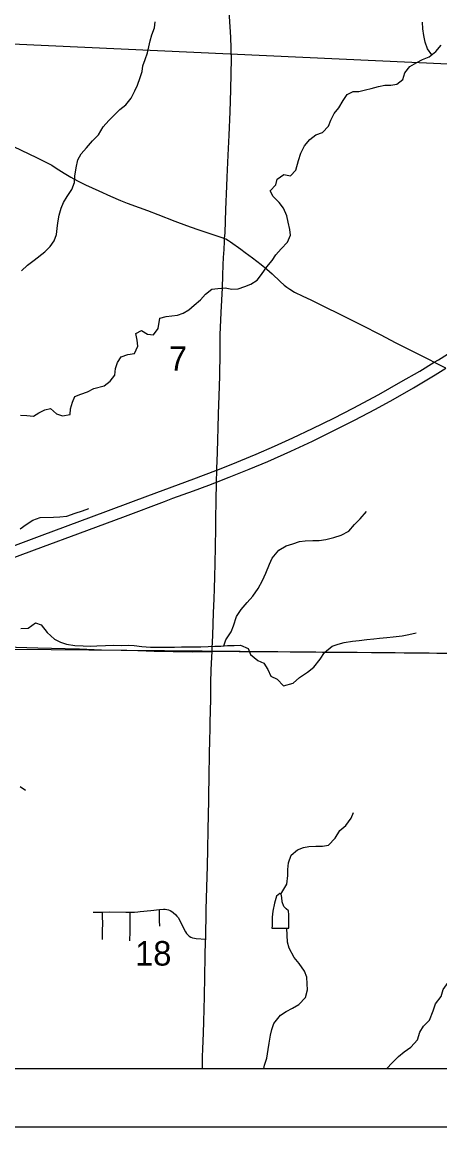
# Model space of a CAD drawing. Extents: x 0 to 34, y 0 to 22.
# Drawn here: x 3.412 to 4.127, y 14 to 15.888 of the extents above; entities that cross this region are included whole.
import ezdxf

# ---------------------------------------------------------------- set-up
doc = ezdxf.new("R2010")
doc.units = 0
for name, color, linetype in [('Default', 7, 'Continuous'), ('GM_X_County_Road', 7, 'Continuous'), ('GM_X_Interstate_Route', 7, 'Continuous'), ('GM_X_Minor_Lake', 7, 'Continuous'), ('GM_X_Minor_River', 7, 'Continuous'), ('GM_X_Section', 7, 'Continuous'), ('GM_X_Section_Text', 7, 'Continuous'), ('GM_X_State_Route', 7, 'Continuous'), ('GM_X_Township_Road', 7, 'Continuous'), ('SH_Cut_Line', 7, 'Continuous'), ('SH_Data', 7, 'Continuous')]:
    doc.layers.add(name, color=color, linetype=linetype)

msp = doc.modelspace()

# ---------------------------------------------------------------- linework, layer by layer
at = {"layer": 'Default'}
msp.add_lwpolyline([(3.1977, 14.1), (4.2188, 14.1), (4.2381, 14.8083), (3.2026, 14.8175)], close=True, dxfattribs=at)
at = {"layer": 'GM_X_County_Road'}
for points in [[(3.3832, 14.8203), (3.4391, 14.8187), (3.4857, 14.8175), (3.5105, 14.8167), (3.5478, 14.8153), (3.5819, 14.8144), (3.6099, 14.8139), (3.6382, 14.8131), (3.6542, 14.8128), (3.6706, 14.8125), (3.6856, 14.8121), (3.7033, 14.8116), (3.7278, 14.8121), (3.7371, 14.8123)], [(3.7371, 14.8123), (3.7464, 14.8126), (3.7587, 14.8126), (3.7836, 14.8124), (3.8053, 14.8122), (3.8344, 14.812), (3.8706, 14.8118), (3.8962, 14.8116), (3.9262, 14.8114), (3.9511, 14.8109), (3.9666, 14.8109), (3.9852, 14.811), (4.01, 14.8107), (4.0504, 14.8104), (4.0659, 14.8101), (4.0876, 14.8099), (4.1031, 14.8098), (4.1217, 14.8097), (4.1652, 14.8095)]]:
    msp.add_lwpolyline(points, dxfattribs=at)
at = {"layer": 'GM_X_Interstate_Route'}
for points in [[(4.6269, 16.8701), (3.6554, 16.8713), (3.6203, 16.8714), (3.2115, 16.8719), (3.2111, 16.7578), (3.2098, 15.7617), (3.2042, 14.9221), (3.2041, 14.9016), (3.2037, 14.7782), (3.2011, 14.1), (8.2568, 14.1)], [(3.3853, 14.9885), (3.4144, 14.9993), (3.4465, 15.0112), (3.531, 15.0424), (3.627, 15.0785), (3.7057, 15.1075), (3.7436, 15.1216), (3.7455, 15.1223), (3.7697, 15.1318), (3.8128, 15.1496), (3.8442, 15.163), (3.8754, 15.1771), (3.9091, 15.1931), (3.9453, 15.211), (3.9785, 15.2281), (4.0223, 15.2516), (4.0603, 15.2729), (4.0926, 15.2915), (4.1173, 15.3065), (4.1245, 15.3109), (4.1614, 15.334)], [(3.742, 15.1007), (3.7449, 15.1018), (3.7663, 15.11), (3.8009, 15.1238), (3.8324, 15.1371), (3.8721, 15.1547), (3.9087, 15.1717), (3.9478, 15.1908), (3.981, 15.2076), (4.0168, 15.2263), (4.0467, 15.2427), (4.0817, 15.2628), (4.1191, 15.2849), (4.1373, 15.2963)], [(3.3237, 14.9455), (3.449, 14.9917), (3.5073, 15.0132), (3.5889, 15.0436), (3.6559, 15.0684), (3.6703, 15.0741), (3.6878, 15.0806), (3.7054, 15.0868), (3.7316, 15.0966), (3.742, 15.1007)]]:
    msp.add_lwpolyline(points, dxfattribs=at)
at = {"layer": 'GM_X_Minor_Lake'}
for points in [[(3.8687, 14.3394), (3.8683, 14.353), (3.8686, 14.3621), (3.8678, 14.3693), (3.864, 14.3727), (3.8598, 14.3765), (3.8572, 14.3845), (3.8568, 14.392), (3.8556, 14.3974), (3.853, 14.3985), (3.8473, 14.3943), (3.8439, 14.3821), (3.8413, 14.3685), (3.8398, 14.3582), (3.8398, 14.3438)], [(3.8687, 14.3393), (3.8683, 14.353), (3.8686, 14.3621), (3.8678, 14.3693), (3.864, 14.3727), (3.8598, 14.3765), (3.8572, 14.3845), (3.8568, 14.392), (3.8556, 14.3974), (3.853, 14.3985), (3.8473, 14.3943), (3.8439, 14.3821), (3.8413, 14.3685), (3.8398, 14.3582), (3.8398, 14.3438)], [(3.8398, 14.3438), (3.8396, 14.3396), (3.8687, 14.3394)]]:
    msp.add_lwpolyline(points, dxfattribs=at)
at = {"layer": 'GM_X_Minor_River'}
for points in [[(3.6175, 15.8032), (3.619, 15.8131), (3.6225, 15.8237), (3.6268, 15.835), (3.6292, 15.8456), (3.6311, 15.8555), (3.6339, 15.8657), (3.6385, 15.8782), (3.6398, 15.888)], [(4.1131, 15.832), (4.1059, 15.8421), (4.1018, 15.8532), (4.0992, 15.8646), (4.0975, 15.8764), (4.0972, 15.8877)], [(3.8649, 15.5565), (3.8593, 15.5698), (3.8518, 15.5794), (3.8417, 15.5897), (3.8365, 15.5996), (3.846, 15.6094), (3.8484, 15.6196), (3.8598, 15.6271), (3.8712, 15.6251), (3.8803, 15.6349), (3.885, 15.6511), (3.8889, 15.6636), (3.8954, 15.6765), (3.9046, 15.687), (3.9149, 15.6952), (3.9259, 15.6993), (3.9362, 15.7098), (3.9405, 15.72), (3.9463, 15.7314), (3.9539, 15.7412), (3.9616, 15.754), (3.9685, 15.7642), (3.9784, 15.769), (3.9882, 15.7693), (3.9996, 15.7718), (4.0095, 15.774), (4.0216, 15.7777), (4.0326, 15.7802), (4.0432, 15.7801), (4.0535, 15.7819), (4.0634, 15.7898), (4.0669, 15.8008), (4.0753, 15.8117), (4.0875, 15.8184), (4.0974, 15.824), (4.1088, 15.8284), (4.1198, 15.8374), (4.129, 15.8483)], [(3.4112, 15.4626), (3.4215, 15.4724), (3.433, 15.481), (3.4509, 15.4949), (3.4604, 15.5042), (3.4669, 15.514), (3.4708, 15.5246), (3.4724, 15.5349), (3.4733, 15.5447), (3.4756, 15.558), (3.4788, 15.5697), (3.483, 15.5795), (3.4892, 15.5897), (3.4972, 15.6018), (3.5019, 15.6135), (3.5023, 15.6245), (3.5044, 15.6389), (3.5075, 15.6525), (3.5133, 15.6627), (3.5221, 15.6729), (3.5328, 15.6849), (3.5431, 15.6951), (3.5511, 15.7086), (3.5603, 15.7196), (3.5699, 15.7286), (3.5794, 15.7383), (3.5897, 15.7462), (3.5989, 15.7579), (3.6051, 15.77), (3.6097, 15.7802), (3.614, 15.793), (3.6175, 15.8032)], [(3.4095, 15.216), (3.4205, 15.2155), (3.4315, 15.2146), (3.441, 15.2198), (3.4509, 15.2254), (3.4607, 15.2272), (3.4713, 15.2184), (3.4811, 15.2149), (3.4943, 15.217), (3.4952, 15.2269), (3.4983, 15.2383), (3.5022, 15.2481), (3.5128, 15.2522), (3.5238, 15.2562), (3.5349, 15.2614), (3.5527, 15.2662), (3.5626, 15.2744), (3.5706, 15.2846), (3.5719, 15.2956), (3.5754, 15.3058), (3.5819, 15.316), (3.5929, 15.3197), (3.6043, 15.3215), (3.6104, 15.3339), (3.609, 15.3442), (3.6065, 15.3556), (3.6164, 15.3608), (3.6269, 15.3543), (3.6371, 15.3534), (3.6448, 15.3643), (3.648, 15.3818), (3.6586, 15.3847), (3.6681, 15.3857), (3.6783, 15.3868), (3.6878, 15.3905), (3.6973, 15.3961), (3.7068, 15.4043), (3.7175, 15.4133), (3.7259, 15.4231), (3.7366, 15.4314), (3.7468, 15.4324), (3.7593, 15.4334), (3.7711, 15.4314), (3.782, 15.4321), (3.7931, 15.4357), (3.8037, 15.4398), (3.8144, 15.4469), (3.822, 15.4567), (3.8308, 15.4695), (3.84, 15.4804), (3.8462, 15.4902), (3.8553, 15.5004), (3.8664, 15.5117), (3.8714, 15.5234), (3.87, 15.5336), (3.8675, 15.5458), (3.8649, 15.5565)], [(3.4088, 15.0221), (3.419, 15.0293), (3.4308, 15.0369), (3.4429, 15.0415), (3.4657, 15.0416), (3.4767, 15.0424), (3.4888, 15.0435), (3.5032, 15.0485), (3.5157, 15.0527), (3.5263, 15.0566)], [(3.7571, 14.8218), (3.7606, 14.8323), (3.7701, 14.846), (3.7738, 14.8562), (3.7787, 14.8722), (3.787, 14.8843), (3.7973, 14.8958), (3.8067, 14.9068), (3.8158, 14.9197), (3.8233, 14.9334), (3.829, 14.9459), (3.8354, 14.9615), (3.8399, 14.9718), (3.8516, 14.9855), (3.8641, 14.9927), (3.8755, 14.9965), (3.8868, 15), (3.8963, 15.0015), (3.9096, 15.002), (3.9202, 15.002), (3.932, 15.0039), (3.9452, 15.007), (3.9578, 15.0108), (3.971, 15.0181), (3.9808, 15.0295), (3.9903, 15.039), (4.0013, 15.0512)], [(3.4101, 14.8517), (3.4226, 14.8521), (3.4351, 14.8613), (3.4446, 14.8579), (3.4552, 14.845), (3.4678, 14.8333), (3.4777, 14.828), (3.4883, 14.825), (3.5023, 14.8228), (3.5168, 14.8217), (3.5289, 14.8213), (3.5399, 14.8217), (3.5547, 14.8225), (3.5687, 14.823), (3.5824, 14.8226), (3.5934, 14.823), (3.604, 14.8223), (3.6173, 14.8208), (3.6321, 14.8197), (3.6484, 14.8194), (3.6579, 14.8194), (3.6727, 14.8199), (3.6848, 14.8203), (3.7182, 14.8204), (3.7307, 14.8208), (3.7421, 14.8212), (3.752, 14.8212), (3.7637, 14.8224), (3.7751, 14.8228), (3.7857, 14.8232), (3.799, 14.8176), (3.8032, 14.807), (3.8154, 14.7968), (3.8256, 14.7926), (3.8325, 14.7817), (3.8378, 14.7699), (3.8488, 14.765), (3.8595, 14.7537), (3.8758, 14.7579), (3.8868, 14.7678), (3.9004, 14.7769), (3.9114, 14.7853), (3.9223, 14.7994), (3.9295, 14.8104), (3.9428, 14.8211), (3.953, 14.8249), (3.9632, 14.8276), (3.9773, 14.8299), (3.989, 14.8311), (4.0019, 14.8326), (4.0137, 14.8338), (4.0235, 14.835), (4.036, 14.8362), (4.047, 14.8373), (4.0626, 14.8393), (4.0736, 14.8412)], [(4.0736, 14.8412), (4.0865, 14.8443)], [(3.4086, 14.5815), (3.4181, 14.5755)], [(3.8548, 14.3977), (3.865, 14.4148), (3.8669, 14.4293), (3.8669, 14.4395), (3.868, 14.4513), (3.8725, 14.4642), (3.8831, 14.4733), (3.8933, 14.4771), (3.9028, 14.4791), (3.9146, 14.4799), (3.9259, 14.4799), (3.9362, 14.4811), (3.9479, 14.4936), (3.9558, 14.5066), (3.966, 14.5149), (3.9751, 14.5275), (3.9789, 14.537)], [(3.8255, 14.1), (3.8269, 14.1055), (3.8306, 14.1176), (3.8333, 14.1321), (3.8351, 14.1431), (3.8374, 14.1567), (3.8392, 14.1662), (3.843, 14.1769), (3.8543, 14.1909), (3.8642, 14.1974), (3.8748, 14.2031), (3.8854, 14.2092), (3.8971, 14.221), (3.9005, 14.2343), (3.9001, 14.2446), (3.8993, 14.256), (3.8951, 14.2658), (3.8863, 14.2791), (3.8779, 14.2893), (3.8692, 14.3052), (3.8661, 14.3154), (3.8649, 14.3394)], [(4.0362, 14.1), (4.0363, 14.1), (4.045, 14.1096), (4.056, 14.1202), (4.0658, 14.1282), (4.0772, 14.1362), (4.0885, 14.1488), (4.0926, 14.1621), (4.0987, 14.172), (4.1089, 14.1826), (4.1153, 14.1982), (4.1194, 14.21), (4.1289, 14.2225), (4.1323, 14.2347), (4.1413, 14.2468), (4.1553, 14.2571)]]:
    msp.add_lwpolyline(points, dxfattribs=at)
at = {"layer": 'GM_X_Section'}
for points in [[(4.2148, 16.747), (4.2083, 16.8683), (4.1045, 16.8706), (3.2153, 16.8759), (3.2082, 15.8593), (4.2651, 15.8107), (4.2549, 16), (4.1282, 16), (4.1282, 16.747)], [(3.2082, 15.8593), (4.2651, 15.8107), (4.2381, 14.8083), (3.2026, 14.8175), (3.2029, 14.8323), (3.2075, 15.8525)]]:
    msp.add_lwpolyline(points, close=True, dxfattribs=at)
at = {"layer": 'GM_X_State_Route'}
msp.add_lwpolyline([(3.7206, 14.1), (3.721, 14.1203), (3.7214, 14.1327), (3.7223, 14.1607), (3.7228, 14.1794), (3.7241, 14.2229), (3.7256, 14.2913), (3.7262, 14.3192), (3.7263, 14.321), (3.7273, 14.3715), (3.7282, 14.4088), (3.7291, 14.446), (3.7297, 14.474), (3.7304, 14.5082), (3.7314, 14.5578), (3.7323, 14.6075), (3.7327, 14.6291), (3.733, 14.6383), (3.7333, 14.6598), (3.7337, 14.6815), (3.734, 14.6907), (3.7348, 14.7311), (3.7353, 14.759), (3.7358, 14.7808), (3.7366, 14.8025), (3.7371, 14.8123), (3.7374, 14.818), (3.7383, 14.8397), (3.7389, 14.8597), (3.7398, 14.8783), (3.7408, 14.9024), (3.7413, 14.9193), (3.742, 14.9404), (3.7426, 14.9622), (3.7433, 14.9914), (3.7437, 15.0225), (3.7436, 15.0437), (3.744, 15.0654), (3.7442, 15.0778), (3.7446, 15.0933), (3.7449, 15.1018), (3.7455, 15.1223), (3.7456, 15.1244), (3.7464, 15.1523), (3.7471, 15.1746), (3.7476, 15.194), (3.7483, 15.2183), (3.7492, 15.2493), (3.7502, 15.283), (3.7513, 15.3229), (3.7511, 15.3536), (3.7528, 15.3914), (3.7537, 15.4125), (3.7548, 15.4336), (3.7557, 15.455), (3.7564, 15.4728), (3.757, 15.4853), (3.7576, 15.4993), (3.7583, 15.5127), (3.7587, 15.5179), (3.7593, 15.5277), (3.7609, 15.5673), (3.7625, 15.6075), (3.7632, 15.623), (3.7649, 15.6602), (3.7664, 15.6943), (3.7679, 15.7346), (3.769, 15.7719), (3.77, 15.7998), (3.7704, 15.8246), (3.7701, 15.8432), (3.7693, 15.8618), (3.7655, 15.9238)], dxfattribs=at)
at = {"layer": 'GM_X_Township_Road'}
for points in [[(3.3975, 15.6751), (3.4369, 15.6564), (3.4483, 15.6509), (3.4562, 15.6469), (3.4632, 15.643), (3.4705, 15.6384), (3.4843, 15.6297), (3.4957, 15.6228), (3.5068, 15.6163), (3.5208, 15.6095), (3.5434, 15.5992), (3.5632, 15.5902), (3.5803, 15.583), (3.5919, 15.5786), (3.6123, 15.5711), (3.6269, 15.5656), (3.6442, 15.5588), (3.6733, 15.5477), (3.6936, 15.5399), (3.7111, 15.5337), (3.7539, 15.5199), (3.7587, 15.5179)], [(3.7587, 15.5179), (3.7608, 15.5171), (3.7651, 15.5145), (3.7689, 15.5121), (3.7864, 15.4995), (3.7939, 15.494), (3.8064, 15.4849), (3.8212, 15.4736), (3.8307, 15.4656), (3.84, 15.4573), (3.8535, 15.4446), (3.8604, 15.4384), (3.8653, 15.4346), (3.8704, 15.4311), (3.8784, 15.4264), (3.8923, 15.4196), (3.9063, 15.413), (3.9314, 15.4008), (3.9536, 15.3897), (3.9925, 15.3702), (4.0256, 15.3532), (4.0504, 15.3403), (4.1087, 15.311), (4.1173, 15.3065), (4.1363, 15.2968)], [(3.534, 14.3667), (3.5413, 14.3669), (3.5479, 14.367), (3.5499, 14.367)], [(3.5497, 14.3202), (3.55, 14.3354), (3.5501, 14.3476), (3.55, 14.3597), (3.5499, 14.367)], [(3.5499, 14.367), (3.5616, 14.3672), (3.5894, 14.3669), (3.5971, 14.3669)], [(3.5965, 14.3181), (3.5969, 14.3337), (3.597, 14.3587), (3.5971, 14.3669)], [(3.5971, 14.3669), (3.5991, 14.3669), (3.6044, 14.3671), (3.6101, 14.3675), (3.6144, 14.3679), (3.6326, 14.3699), (3.6474, 14.3716)], [(3.6477, 14.3432), (3.6473, 14.3524), (3.6474, 14.3647), (3.6474, 14.3716)], [(3.6474, 14.3716), (3.654, 14.3721), (3.657, 14.372), (3.6599, 14.3715), (3.6628, 14.3707), (3.6655, 14.3695), (3.6681, 14.3681), (3.6706, 14.3664), (3.6751, 14.3624), (3.6771, 14.3602), (3.6789, 14.3577), (3.6818, 14.3525), (3.6886, 14.3386), (3.6916, 14.333), (3.6934, 14.3304), (3.6955, 14.328), (3.698, 14.326), (3.7008, 14.3244), (3.7038, 14.3232), (3.7069, 14.3224), (3.71, 14.3219), (3.7263, 14.321)]]:
    msp.add_lwpolyline(points, dxfattribs=at)
at = {"layer": 'SH_Cut_Line'}
msp.add_lwpolyline([(2.1, 20.9), (2.1, 14.1), (8.2568, 14.1)], dxfattribs=at)
at = {"layer": 'SH_Data'}
for p, q in [((2.1, 14.1), (8.9, 14.1)), ((2, 14), (9, 14))]:
    msp.add_line(p, q, dxfattribs=at)

# ---------------------------------------------------------------- texts
at = {"layer": 'GM_X_Section_Text'}
for s, height, p in [('7', 0.0419, (3.6633, 15.2919)), ('18', 0.04186, (3.6054, 14.2756))]:
    msp.add_text(s, height=height, rotation=0, dxfattribs=at).set_placement(p)

doc.saveas('drawing.dxf')
